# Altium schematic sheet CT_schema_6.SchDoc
size 371 x 245 mm
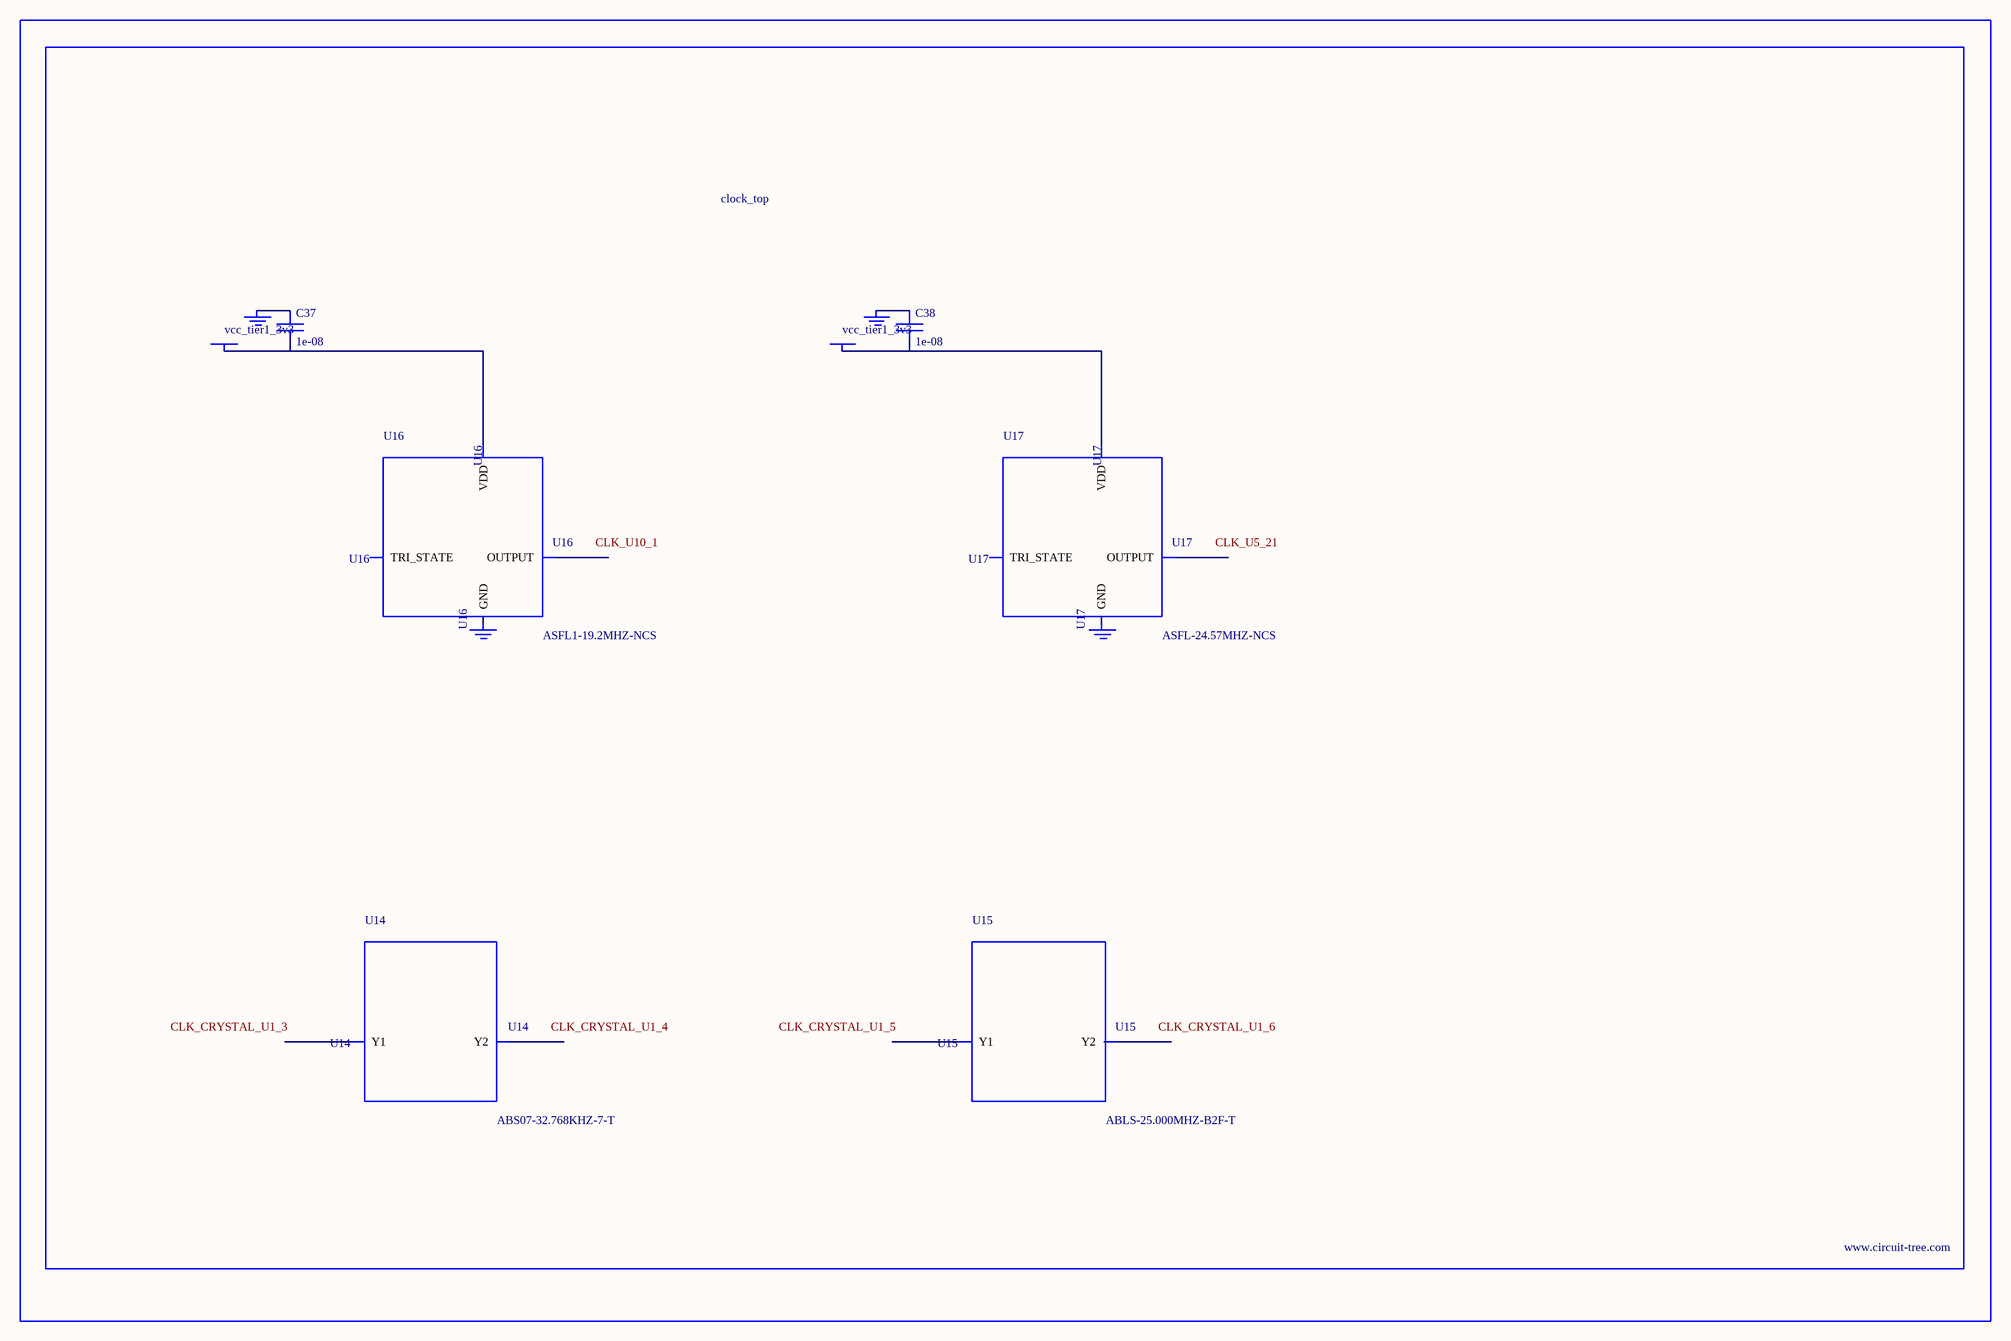
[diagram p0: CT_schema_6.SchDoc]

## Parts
BORDER5  (no value)
C37  1e-08  [C0402]
C38  1e-08  [C0402]
GND_INSTANCE_5_0  (no value)
GND_INSTANCE_5_1  (no value)
GND_INSTANCE_5_2  (no value)
GND_INSTANCE_5_3  (no value)
POWER_INSTANCE_5_0  vcc_tier1_3v3
POWER_INSTANCE_5_1  vcc_tier1_3v3
U14  ABS07-32.768KHZ-7-T  [ABS07-32.768KHZ-7-T]
U15  ABLS-25.000MHZ-B2F-T  [ABLS-25.000MHZ-B2F-T]
U16  ASFL1-19.2MHZ-NCS  [ASFL1]
U17  ASFL-24.57MHZ-NCS  [ASFL1]

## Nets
NetC37_1: C37.1 GND_INSTANCE_5_0.0(GND)
NetC37_2: C37.2 POWER_INSTANCE_5_0.0(PWR) U16.4(VDD)
NetC38_1: C38.1 GND_INSTANCE_5_2.0(GND)
NetC38_2: C38.2 POWER_INSTANCE_5_1.0(PWR) U17.4(VDD)

Not connected (* = marked no-connect by the designer): GND_INSTANCE_5_1 0(GND); GND_INSTANCE_5_3 0(GND); U14 1(Y1) 2(Y2); U15 1(Y1) 2(Y2); U16 1(TRI_STATE) 2(GND) 3(OUTPUT); U17 1(TRI_STATE) 2(GND) 3(OUTPUT)

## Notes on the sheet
- Labels drawn without touching a wire or pin: CLK_CRYSTAL_U1_3, CLK_CRYSTAL_U1_4, CLK_CRYSTAL_U1_5, CLK_CRYSTAL_U1_6, CLK_U5_21, CLK_U10_1

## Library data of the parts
BORDER5 = BORDER_PAGE5
C37 C38 = C0402C103K3RAC
GND_INSTANCE_5_0-GND_INSTANCE_5_3 = GND
POWER_INSTANCE_5_0 POWER_INSTANCE_5_1 = PWR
